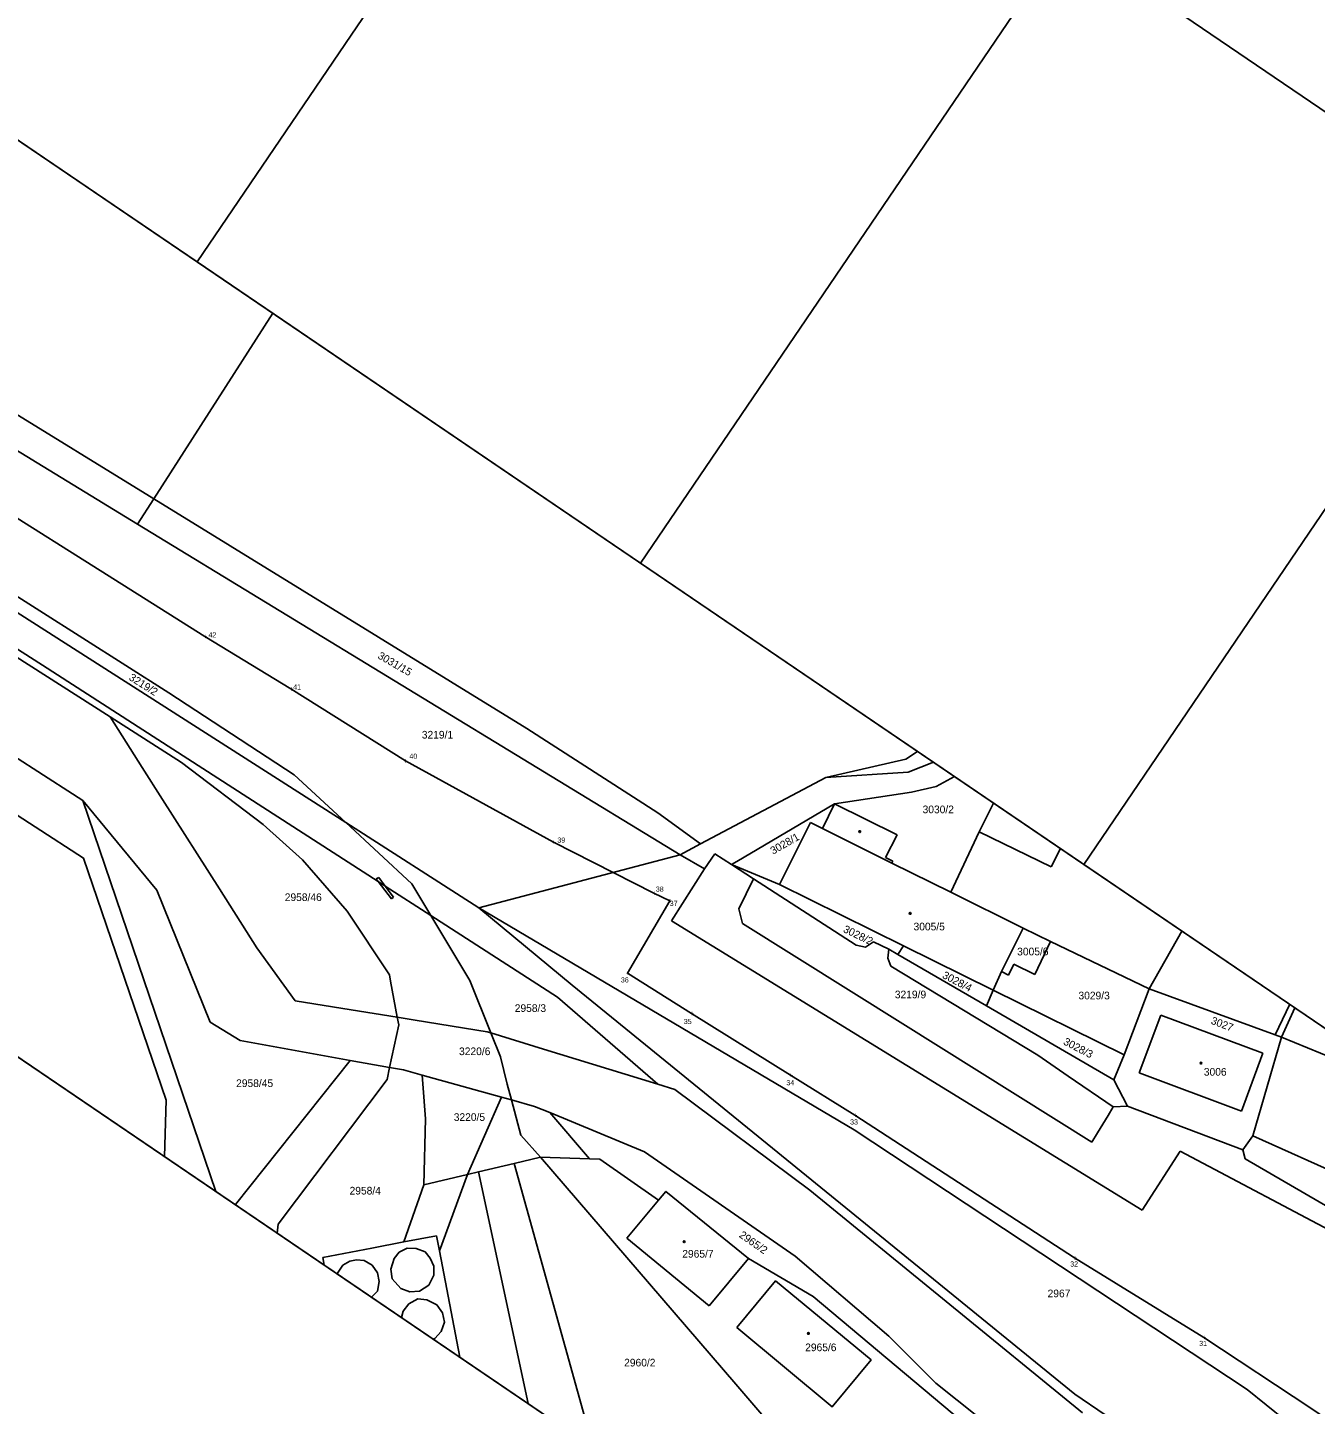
# Model space of a CAD drawing. Extents: x -621058 to -620110, y -1122807 to -1122030.
# Drawn here: x -620573.6 to -620321.3, y -1122671.6 to -1122402 of the extents above; entities that cross this region are included whole.
import ezdxf

# ---------------------------------------------------------------- set-up
doc = ezdxf.new("R2010")
doc.units = 0
for name, color, linetype in [('060601_EOV', 7, 'Continuous'), ('BODY', 7, 'Continuous'), ('BODY POPIS', 7, 'Continuous'), ('RÁMY', 7, 'Continuous'), ('Vrstva 53', 7, 'Continuous'), ('Vrstva 55', 7, 'Continuous'), ('Vrstva 56', 7, 'Continuous'), ('Vrstva 57', 7, 'Continuous')]:
    doc.layers.add(name, color=color, linetype=linetype)

msp = doc.modelspace()

# ---------------------------------------------------------------- linework, layer by layer
at = {"layer": '060601_EOV'}
msp.add_lwpolyline([(-620235.16, -1122712.24), (-620240.17, -1122718.34), (-620243.03, -1122716), (-620248.32, -1122722.77), (-620259.89, -1122713.57), (-620277.71, -1122700.9), (-620282.35, -1122705.3), (-620297.82, -1122689.49), (-620304.22, -1122684.86), (-620310.82, -1122680.06), (-620322.23, -1122672.32), (-620343.18, -1122658.46), (-620368.5, -1122642.9), (-620411.56, -1122614.92), (-620424.16, -1122607.09), (-620443.53, -1122595), (-620456.11, -1122587.12), (-620447.82, -1122572.96), (-620450.95, -1122571.45), (-620470.59, -1122561.48), (-620499.61, -1122545.57), (-620522.04, -1122531.47), (-620538.89, -1122521.21), (-620599.21, -1122483.22)], dxfattribs=at)
at = {"layer": 'RÁMY'}
for points in [[(-620974.7, -1122152.91), (-620192.94, -1122683.83), (-620276.37, -1122806.68), (-621058.13, -1122275.76)], [(-620887.83, -1122211.9), (-620192.94, -1122683.83), (-620276.37, -1122806.68), (-620971.26, -1122334.75)], [(-620543.82, -1122266.03), (-620456.95, -1122325.02), (-620540.39, -1122447.87), (-620627.25, -1122388.87)], [(-620456.95, -1122325.02), (-620370.09, -1122384.01), (-620453.52, -1122506.86), (-620540.39, -1122447.87)], [(-620370.09, -1122384.01), (-620283.23, -1122443), (-620366.66, -1122565.85), (-620453.52, -1122506.86)], [(-620283.23, -1122443), (-620196.37, -1122501.99), (-620279.8, -1122624.84), (-620366.66, -1122565.85)]]:
    msp.add_lwpolyline(points, close=True, dxfattribs=at)
at = {"layer": 'Vrstva 53'}
for p, q in [((-620545.92, -1122532.26), (-620679.51, -1122447.56)), ((-620638.48, -1122446.57), (-620552.09, -1122499.2)), ((-620552.09, -1122499.2), (-620445.8, -1122563.95)), ((-620521.41, -1122548.27), (-620545.92, -1122532.26)), ((-620511.29, -1122557.64), (-620521.41, -1122548.27)), ((-620485.21, -1122574.33), (-620511.29, -1122557.64)), ((-620445.8, -1122563.95), (-620440.98, -1122566.69)), ((-620440.98, -1122566.69), (-620438.97, -1122563.76)), ((-620435.69, -1122565.88), (-620438.97, -1122563.76)), ((-620435.69, -1122565.88), (-620431.39, -1122568.66)), ((-620440.98, -1122566.69), (-620447.48, -1122576.88)), ((-620431.39, -1122568.66), (-620434.26, -1122574.5)), ((-620411.71, -1122617.81), (-620485.21, -1122574.33)), ((-620434.26, -1122574.5), (-620433.53, -1122577.42)), ((-620447.48, -1122576.88), (-620355.23, -1122633.54)), ((-620433.53, -1122577.42), (-620402.13, -1122597.06)), ((-620402.13, -1122597.06), (-620365.14, -1122620.19)), ((-620361.94, -1122614.97), (-620364.03, -1122618.38)), ((-620358.11, -1122613.18), (-620360.91, -1122613.28)), ((-620358.11, -1122613.18), (-620335.54, -1122621.75)), ((-620334.71, -1122668.63), (-620411.71, -1122617.81)), ((-620364.03, -1122618.38), (-620365.14, -1122620.19)), ((-620347.83, -1122621.96), (-620355.23, -1122633.54)), ((-620347.83, -1122621.96), (-620296.23, -1122649.3)), ((-620335.09, -1122623.49), (-620335.54, -1122621.75)), ((-620335.09, -1122623.49), (-620318.55, -1122633.1)), ((-620309.9, -1122688.62), (-620334.71, -1122668.63))]:
    msp.add_line(p, q, dxfattribs=at)
at = {"layer": 'Vrstva 55'}
for p, q in [((-620688.16, -1122408.5), (-620548.9, -1122494.24)), ((-620545.92, -1122532.26), (-620679.51, -1122447.56)), ((-620638.48, -1122446.57), (-620552.09, -1122499.2)), ((-620557.45, -1122536.96), (-620684.91, -1122455.63)), ((-620548.9, -1122494.24), (-620525.58, -1122457.92)), ((-620552.09, -1122499.2), (-620548.9, -1122494.24)), ((-620548.9, -1122494.24), (-620475.79, -1122539.24)), ((-620552.09, -1122499.2), (-620445.8, -1122563.95)), ((-620511.29, -1122557.64), (-620587.17, -1122509.18)), ((-620521.41, -1122548.27), (-620545.92, -1122532.26)), ((-620557.45, -1122536.96), (-620551.15, -1122546.87)), ((-620543.5, -1122545.86), (-620557.45, -1122536.96)), ((-620475.79, -1122539.24), (-620450.17, -1122555.76)), ((-620401.53, -1122545.24), (-620399.25, -1122543.72)), ((-620551.15, -1122546.87), (-620547.19, -1122553.1)), ((-620543.5, -1122545.86), (-620527.5, -1122558.02)), ((-620417.25, -1122548.82), (-620401.53, -1122545.24)), ((-620511.29, -1122557.64), (-620521.41, -1122548.27)), ((-620417.25, -1122548.82), (-620441.78, -1122561.82)), ((-620547.19, -1122553.1), (-620536.04, -1122570.64)), ((-620548.28, -1122570.88), (-620562.8, -1122553.35)), ((-620562.8, -1122553.35), (-620536.71, -1122629.87)), ((-620450.17, -1122555.76), (-620441.78, -1122561.82)), ((-620415.52, -1122553.94), (-620434.68, -1122565.28)), ((-620415.52, -1122553.94), (-620417.91, -1122558.83)), ((-620415.52, -1122553.94), (-620403.26, -1122560.03)), ((-620384.37, -1122553.82), (-620387.17, -1122559.43)), ((-620519.77, -1122564.93), (-620527.5, -1122558.02)), ((-620498.35, -1122569.65), (-620511.29, -1122557.64)), ((-620511.29, -1122557.64), (-620485.21, -1122574.33)), ((-620420.27, -1122557.63), (-620426.32, -1122569.77)), ((-620417.91, -1122558.83), (-620420.27, -1122557.63)), ((-620403.26, -1122560.03), (-620405.52, -1122564.49)), ((-620387.17, -1122559.43), (-620392.72, -1122571.3)), ((-620387.17, -1122559.43), (-620373.07, -1122566.34)), ((-620441.78, -1122561.82), (-620445.8, -1122563.95)), ((-620445.8, -1122563.95), (-620440.98, -1122566.69)), ((-620440.98, -1122566.69), (-620438.97, -1122563.76)), ((-620435.69, -1122565.88), (-620438.97, -1122563.76)), ((-620371.29, -1122562.71), (-620373.07, -1122566.34)), ((-620511.02, -1122574.99), (-620519.77, -1122564.93)), ((-620434.68, -1122565.28), (-620435.69, -1122565.88)), ((-620435.69, -1122565.88), (-620426.32, -1122569.77)), ((-620435.69, -1122565.88), (-620431.39, -1122568.66)), ((-620405.52, -1122564.49), (-620404.12, -1122565.22)), ((-620404.12, -1122565.22), (-620404.28, -1122565.56)), ((-620404.28, -1122565.56), (-620392.72, -1122571.3)), ((-620440.98, -1122566.69), (-620447.48, -1122576.88)), ((-620431.39, -1122568.66), (-620434.26, -1122574.5)), ((-620431.39, -1122568.66), (-620411.27, -1122581.65)), ((-620537.83, -1122596.73), (-620548.28, -1122570.88)), ((-620536.04, -1122570.64), (-620528.72, -1122582.15)), ((-620494.61, -1122575.85), (-620498.35, -1122569.65)), ((-620426.32, -1122569.77), (-620402.04, -1122581.77)), ((-620378.57, -1122578.31), (-620392.72, -1122571.3)), ((-620485.21, -1122574.33), (-620466.94, -1122589.51)), ((-620411.71, -1122617.81), (-620485.21, -1122574.33)), ((-620434.26, -1122574.5), (-620433.53, -1122577.42)), ((-620502.74, -1122587.44), (-620511.02, -1122574.99)), ((-620486.95, -1122588.56), (-620494.61, -1122575.85)), ((-620469.8, -1122591.86), (-620494.61, -1122575.85)), ((-620447.48, -1122576.88), (-620355.23, -1122633.54)), ((-620433.53, -1122577.42), (-620402.13, -1122597.06)), ((-620382.82, -1122586.79), (-620378.57, -1122578.31)), ((-620378.57, -1122578.31), (-620373.23, -1122580.96)), ((-620347.47, -1122578.88), (-620353.86, -1122590.22)), ((-620528.72, -1122582.15), (-620521.17, -1122592.53)), ((-620411.27, -1122581.65), (-620409.46, -1122582.07)), ((-620409.46, -1122582.07), (-620407.91, -1122580.98)), ((-620407.91, -1122580.98), (-620404.87, -1122582.42)), ((-620403.1, -1122583.45), (-620404.87, -1122582.42)), ((-620403.1, -1122583.45), (-620402.04, -1122581.77)), ((-620402.04, -1122581.77), (-620384.45, -1122590.46)), ((-620376.29, -1122587.36), (-620373.23, -1122580.96)), ((-620373.23, -1122580.96), (-620353.86, -1122590.22)), ((-620385.78, -1122593.52), (-620403.1, -1122583.45)), ((-620381.45, -1122587.52), (-620380.38, -1122585.36)), ((-620380.38, -1122585.36), (-620376.29, -1122587.36)), ((-620502.51, -1122588.68), (-620502.74, -1122587.44)), ((-620384.45, -1122590.46), (-620382.82, -1122586.79)), ((-620382.82, -1122586.79), (-620381.45, -1122587.52)), ((-620501.2, -1122595.75), (-620502.51, -1122588.68)), ((-620482.88, -1122598.82), (-620486.95, -1122588.56)), ((-620466.94, -1122589.51), (-620368.46, -1122669.58)), ((-620385.78, -1122593.52), (-620384.45, -1122590.46)), ((-620384.45, -1122590.46), (-620358.78, -1122603.15)), ((-620353.86, -1122590.22), (-620358.78, -1122603.15)), ((-620329.18, -1122599.21), (-620353.86, -1122590.22)), ((-620521.17, -1122592.53), (-620510.22, -1122594.3)), ((-620469.8, -1122591.86), (-620450.13, -1122608.86)), ((-620360.83, -1122608.03), (-620385.78, -1122593.52)), ((-620329.18, -1122599.21), (-620326.36, -1122593.22)), ((-620510.22, -1122594.3), (-620501.2, -1122595.75)), ((-620501.2, -1122595.75), (-620497.68, -1122596.32)), ((-620500.92, -1122597.26), (-620501.2, -1122595.75)), ((-620497.68, -1122596.32), (-620483.58, -1122598.6)), ((-620355.84, -1122606.66), (-620351.59, -1122595.35)), ((-620351.59, -1122595.35), (-620331.64, -1122602.77)), ((-620327.97, -1122599.65), (-620325.34, -1122593.91)), ((-620531.96, -1122600.32), (-620537.83, -1122596.73)), ((-620502.69, -1122605.61), (-620500.92, -1122597.26)), ((-620483.58, -1122598.6), (-620482.88, -1122598.82)), ((-620482.88, -1122598.82), (-620472.56, -1122601.98)), ((-620481, -1122603.54), (-620482.88, -1122598.82)), ((-620365.14, -1122620.19), (-620402.13, -1122597.06)), ((-620510.44, -1122604.21), (-620531.96, -1122600.32)), ((-620333.59, -1122619.01), (-620327.97, -1122599.65)), ((-620327.97, -1122599.65), (-620329.18, -1122599.21)), ((-620327.97, -1122599.65), (-620299.9, -1122611.19)), ((-620532.9, -1122632.46), (-620510.44, -1122604.21)), ((-620502.69, -1122605.61), (-620510.44, -1122604.21)), ((-620479.67, -1122608.86), (-620481, -1122603.54)), ((-620472.56, -1122601.98), (-620450.13, -1122608.86)), ((-620360.83, -1122608.03), (-620358.78, -1122603.15)), ((-620331.64, -1122602.77), (-620335.8, -1122614.14)), ((-620503.19, -1122607.95), (-620502.69, -1122605.61)), ((-620500, -1122606.09), (-620502.69, -1122605.61)), ((-620496.31, -1122607.11), (-620500, -1122606.09)), ((-620496.31, -1122607.11), (-620496.18, -1122608.79)), ((-620480.79, -1122611.41), (-620496.31, -1122607.11)), ((-620355.84, -1122606.66), (-620335.8, -1122614.14)), ((-620503.19, -1122607.95), (-620524.52, -1122636.25)), ((-620495.65, -1122615.65), (-620496.18, -1122608.79)), ((-620478.83, -1122611.96), (-620479.67, -1122608.86)), ((-620450.13, -1122608.86), (-620446.79, -1122609.88)), ((-620360.83, -1122608.03), (-620358.11, -1122613.18)), ((-620478.83, -1122611.96), (-620480.79, -1122611.41)), ((-620474.31, -1122613.21), (-620478.83, -1122611.96)), ((-620476.96, -1122618.82), (-620478.83, -1122611.96)), ((-620446.79, -1122609.88), (-620420.38, -1122629.64)), ((-620471.33, -1122614.44), (-620474.31, -1122613.21)), ((-620452.73, -1122622.13), (-620471.33, -1122614.44)), ((-620361.94, -1122614.97), (-620364.03, -1122618.38)), ((-620360.91, -1122613.28), (-620361.94, -1122614.97)), ((-620358.11, -1122613.18), (-620360.91, -1122613.28)), ((-620358.11, -1122613.18), (-620335.54, -1122621.75)), ((-620495.96, -1122628.58), (-620495.65, -1122615.65)), ((-620334.71, -1122668.63), (-620411.71, -1122617.81)), ((-620473.14, -1122623.15), (-620476.96, -1122618.82)), ((-620364.03, -1122618.38), (-620365.14, -1122620.19)), ((-620335.54, -1122621.75), (-620333.59, -1122619.01)), ((-620333.59, -1122619.01), (-620307.23, -1122630.79)), ((-620478.32, -1122624.38), (-620473.14, -1122623.15)), ((-620434.88, -1122667.63), (-620473.14, -1122623.15)), ((-620473.14, -1122623.15), (-620463.51, -1122623.5)), ((-620423.22, -1122642.55), (-620452.73, -1122622.13)), ((-620347.83, -1122621.96), (-620355.23, -1122633.54)), ((-620347.83, -1122621.96), (-620296.23, -1122649.3)), ((-620335.09, -1122623.49), (-620335.54, -1122621.75)), ((-620485.31, -1122626.04), (-620478.32, -1122624.38)), ((-620463.28, -1122678.3), (-620478.32, -1122624.38)), ((-620318.55, -1122633.1), (-620335.09, -1122623.49)), ((-620487.46, -1122626.56), (-620495.96, -1122628.58)), ((-620485.31, -1122626.04), (-620487.46, -1122626.56)), ((-620475.57, -1122671.39), (-620485.31, -1122626.04)), ((-620420.38, -1122629.64), (-620366.98, -1122673.23)), ((-620456.23, -1122639.05), (-620450.04, -1122631.61)), ((-620524.73, -1122638.01), (-620524.52, -1122636.25)), ((-620493.5, -1122638.55), (-620499.9, -1122639.77)), ((-620492.94, -1122641.47), (-620493.5, -1122638.55)), ((-620440.08, -1122652.3), (-620456.23, -1122639.05)), ((-620506.17, -1122640.97), (-620515.78, -1122642.8)), ((-620499.9, -1122639.77), (-620506.17, -1122640.97)), ((-620488.95, -1122662.31), (-620492.94, -1122641.47)), ((-620515.78, -1122642.8), (-620515.5, -1122644.28)), ((-620432.38, -1122643.03), (-620440.08, -1122652.3)), ((-620404.9, -1122658.18), (-620423.22, -1122642.55)), ((-620395.68, -1122667.41), (-620404.9, -1122658.18)), ((-620391.77, -1122717.74), (-620434.88, -1122667.63)), ((-620365.35, -1122691.52), (-620395.68, -1122667.41)), ((-620309.9, -1122688.62), (-620334.71, -1122668.63)), ((-620368.46, -1122669.58), (-620310.57, -1122708.76))]:
    msp.add_line(p, q, dxfattribs=at)
for points in [[(-620562.8, -1122553.35), (-620572.54, -1122547.06), (-620576.58, -1122544.45)], [(-620581.67, -1122552.32), (-620562.67, -1122564.59), (-620546.5, -1122612), (-620546.78, -1122623.03)], [(-620463.51, -1122623.5), (-620461.53, -1122623.57), (-620450.04, -1122631.61)], [(-620450.04, -1122631.61), (-620448.58, -1122629.86), (-620432.38, -1122643.03)], [(-620432.38, -1122643.03), (-620419.73, -1122650.41), (-620372.55, -1122689.97), (-620363.06, -1122698.75), (-620352.08, -1122712.18), (-620349.5, -1122720.4)], [(-620434.7, -1122656.53), (-620427.07, -1122647.39), (-620408.37, -1122662.86), (-620416.01, -1122672.06), (-620434.7, -1122656.53)]]:
    msp.add_lwpolyline(points, dxfattribs=at)
at = {"layer": 'Vrstva 56'}
for p, q in [((-620570.69, -1122526.84), (-620613.12, -1122500)), ((-620504.94, -1122569.2), (-620570.69, -1122526.84)), ((-620417.25, -1122548.82), (-620401.09, -1122547.76)), ((-620401.09, -1122547.76), (-620396.12, -1122545.84)), ((-620395.61, -1122550.55), (-620392.04, -1122548.61)), ((-620415.52, -1122553.94), (-620400.46, -1122551.66)), ((-620400.46, -1122551.66), (-620395.61, -1122550.55)), ((-620404.28, -1122565.56), (-620417.91, -1122558.83)), ((-620485.21, -1122574.33), (-620445.8, -1122563.95)), ((-620505.32, -1122568.68), (-620504.84, -1122568.4)), ((-620504.94, -1122569.2), (-620505.32, -1122568.68)), ((-620503.56, -1122570.07), (-620504.94, -1122569.2)), ((-620502.33, -1122572.56), (-620504.94, -1122569.2)), ((-620504.84, -1122568.4), (-620503.56, -1122570.07)), ((-620494.61, -1122575.85), (-620503.56, -1122570.07)), ((-620503.56, -1122570.07), (-620501.96, -1122572.22)), ((-620501.96, -1122572.22), (-620502.33, -1122572.56)), ((-620405.1, -1122584.22), (-620404.87, -1122582.42)), ((-620404.53, -1122585.79), (-620405.1, -1122584.22)), ((-620375.73, -1122603.21), (-620404.53, -1122585.79)), ((-620369.73, -1122607.28), (-620375.73, -1122603.21)), ((-620360.91, -1122613.28), (-620369.73, -1122607.28)), ((-620487.46, -1122626.56), (-620480.79, -1122611.41)), ((-620471.33, -1122614.44), (-620463.51, -1122623.5)), ((-620495.96, -1122628.58), (-620499.9, -1122639.77)), ((-620487.46, -1122626.56), (-620492.94, -1122641.47)), ((-620501.82, -1122643), (-620500.81, -1122641.76)), ((-620500.81, -1122641.76), (-620499.26, -1122640.98)), ((-620499.26, -1122640.98), (-620497.47, -1122641.06)), ((-620497.47, -1122641.06), (-620495.76, -1122641.68)), ((-620495.76, -1122641.68), (-620494.75, -1122642.92)), ((-620512.93, -1122645.88), (-620511.84, -1122644.32)), ((-620511.84, -1122644.32), (-620510.52, -1122643.55)), ((-620510.52, -1122643.55), (-620509.2, -1122643.23)), ((-620509.2, -1122643.23), (-620507.65, -1122643.39)), ((-620507.65, -1122643.39), (-620506.09, -1122644.32)), ((-620506.09, -1122644.32), (-620505.08, -1122645.8)), ((-620502.44, -1122645.1), (-620501.82, -1122643)), ((-620494.75, -1122642.92), (-620494.06, -1122644.48)), ((-620494.06, -1122644.48), (-620494.06, -1122646.26)), ((-620512.93, -1122646.02), (-620512.93, -1122645.88)), ((-620505.08, -1122645.8), (-620504.77, -1122647.51)), ((-620504.77, -1122647.51), (-620505.08, -1122649.37)), ((-620502.21, -1122646.96), (-620502.44, -1122645.1)), ((-620500.5, -1122648.9), (-620502.21, -1122646.96)), ((-620494.06, -1122646.26), (-620494.99, -1122648.21)), ((-620505.08, -1122649.37), (-620506.22, -1122650.58)), ((-620498.71, -1122649.52), (-620500.5, -1122648.9)), ((-620496.85, -1122649.37), (-620498.71, -1122649.52)), ((-620494.99, -1122648.21), (-620496.85, -1122649.37)), ((-620500.03, -1122653.33), (-620498.95, -1122651.85)), ((-620498.95, -1122651.85), (-620497.16, -1122650.92)), ((-620497.16, -1122650.92), (-620495.38, -1122651.08)), ((-620495.38, -1122651.08), (-620493.43, -1122652.09)), ((-620493.43, -1122652.09), (-620492.35, -1122653.64)), ((-620500.34, -1122654.57), (-620500.03, -1122653.33)), ((-620491.96, -1122655.5), (-620492.58, -1122657.29)), ((-620492.35, -1122653.64), (-620491.96, -1122655.5)), ((-620492.58, -1122657.29), (-620493.82, -1122658.69)), ((-620493.82, -1122658.69), (-620494.1, -1122658.81))]:
    msp.add_line(p, q, dxfattribs=at)
at = {"layer": 'Vrstva 57'}
for centre in [(-620410.59, -1122559.41), (-620400.71, -1122575.42), (-620343.73, -1122604.73), (-620444.98, -1122639.7), (-620420.65, -1122657.67)]:
    msp.add_circle(centre, 0.175, dxfattribs=at)

# ---------------------------------------------------------------- texts
at = {"layer": 'BODY'}
for p in [(-620539.22, -1122521.71), (-620522.37, -1122531.97), (-620499.94, -1122546.07), (-620470.93, -1122561.98), (-620451.28, -1122571.95), (-620448.16, -1122573.46), (-620456.44, -1122587.62), (-620443.86, -1122595.5), (-620424.49, -1122607.59), (-620411.89, -1122615.42), (-620368.83, -1122643.4), (-620343.51, -1122658.96)]:
    msp.add_text('+', height=1, dxfattribs=at).set_placement(p)
at = {"layer": 'BODY POPIS'}
for s, p in [('42', (-620538.18, -1122521.38)), ('41', (-620521.59, -1122531.59)), ('40', (-620498.82, -1122545.15)), ('39', (-620469.83, -1122561.57)), ('38', (-620450.54, -1122571.17)), ('37', (-620447.82, -1122573.96)), ('36', (-620457.39, -1122588.95)), ('35', (-620445.05, -1122597.09)), ('34', (-620424.96, -1122609.08)), ('33', (-620412.48, -1122616.76)), ('32', (-620369.36, -1122644.58)), ('31', (-620344.09, -1122660.13))]:
    msp.add_text(s, height=1, dxfattribs=at).set_placement(p)
at = {"layer": 'Vrstva 57'}
for s, rotation, p in [('3031/15', 330.0385, (-620505.16, -1122525.39)), ('3219/2', 327.6, (-620553.91, -1122529.6)), ('3028/1', 29.7, (-620427.58, -1122563.94)), ('3028/2', 334.1384, (-620413.98, -1122579.01)), ('3005/6', 0.4373, (-620379.74, -1122583.66)), ('3028/4', 332.452, (-620394.55, -1122587.99)), ('3027', 339.3, (-620341.92, -1122597)), ('3028/3', 332.5324, (-620370.84, -1122601)), ('2965/2', 325.0126, (-620434.36, -1122638.71))]:
    msp.add_text(s, height=1.5, rotation=rotation, dxfattribs=at).set_placement(p)
for s, p in [('3219/1', (-620496.39, -1122541.19)), ('3030/2', (-620398.28, -1122555.81)), ('2958/46', (-620523.24, -1122573.01)), ('3005/5', (-620400.05, -1122578.75)), ('3219/9', (-620403.72, -1122592.05)), ('3029/3', (-620367.74, -1122592.26)), ('2958/3', (-620478.18, -1122594.72)), ('3220/6', (-620489.09, -1122603.18)), ('3006', (-620343.18, -1122607.2)), ('2958/45', (-620532.77, -1122609.42)), ('3220/5', (-620490.13, -1122616.06)), ('2958/4', (-620510.54, -1122630.47)), ('2965/7', (-620445.36, -1122642.83)), ('2967', (-620373.79, -1122650.59)), ('2965/6', (-620421.28, -1122661.15)), ('2960/2', (-620456.75, -1122664.14))]:
    msp.add_text(s, height=1.5, dxfattribs=at).set_placement(p)

doc.saveas('drawing.dxf')
